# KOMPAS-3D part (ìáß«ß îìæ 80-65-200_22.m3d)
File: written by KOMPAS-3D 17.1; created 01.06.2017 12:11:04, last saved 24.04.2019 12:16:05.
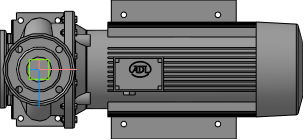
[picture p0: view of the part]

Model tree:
1. Операция без истории:2

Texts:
  ООО АДЛ ГРУПП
